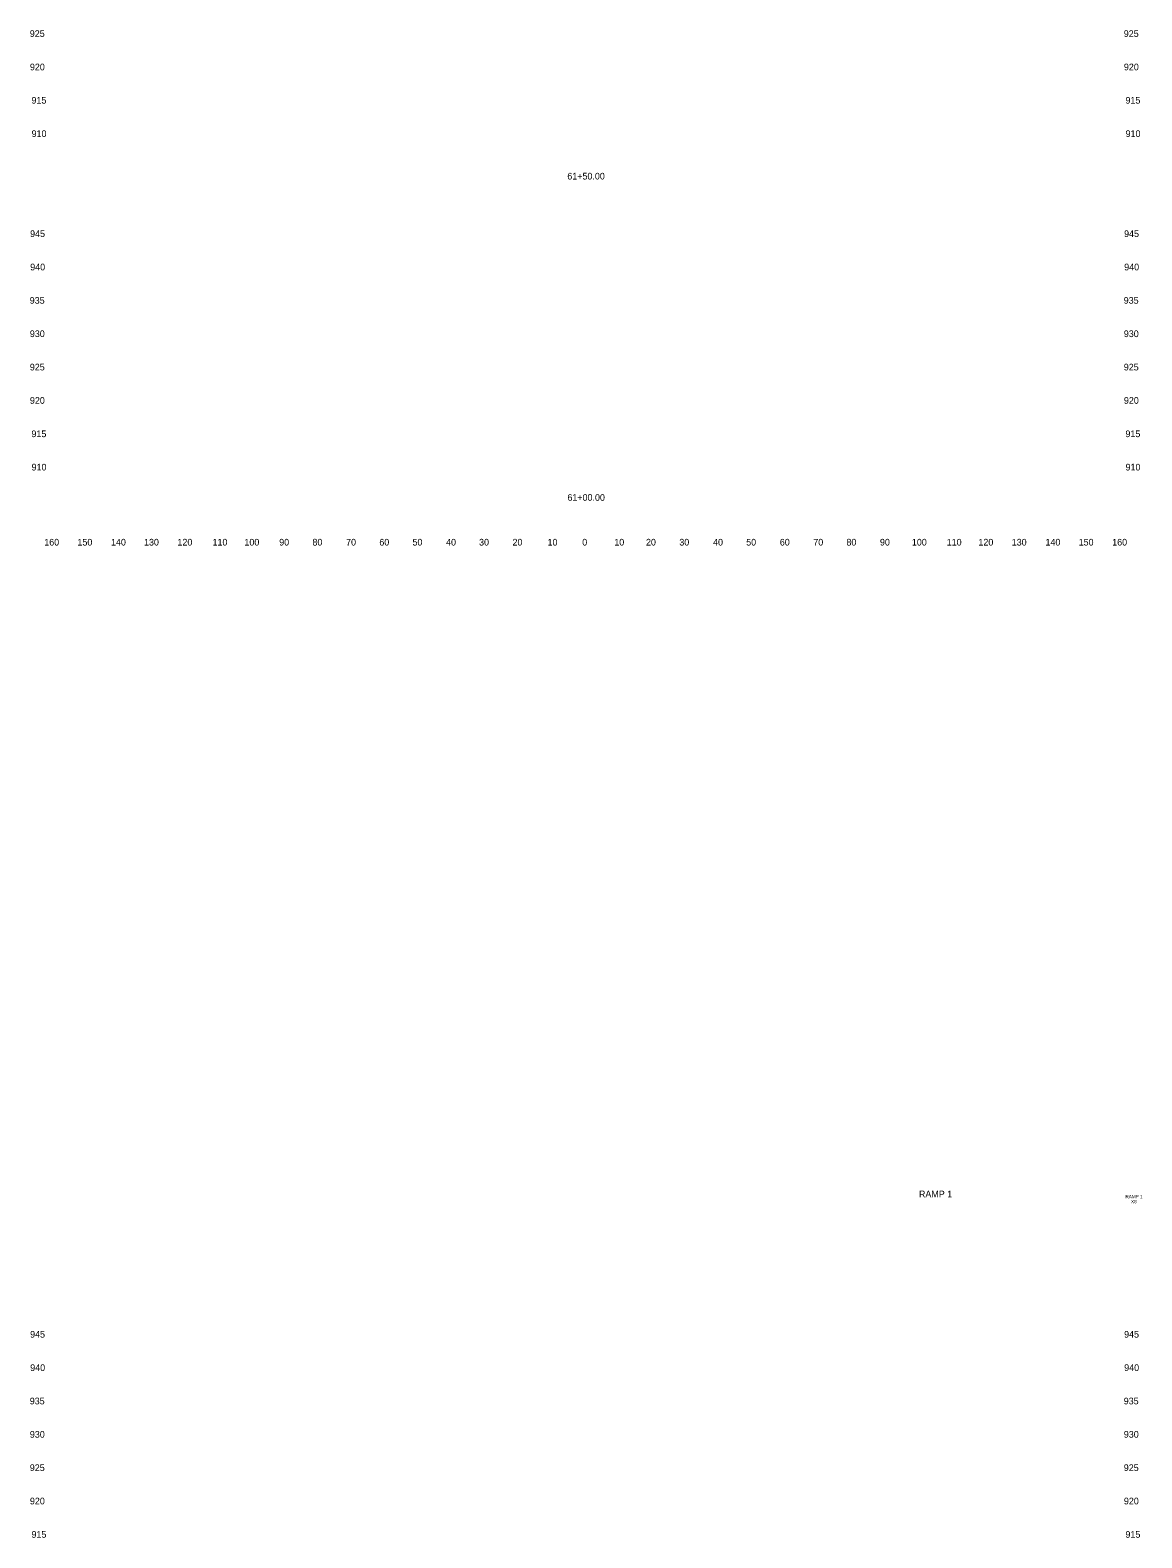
# Model space of a CAD drawing. Extents: x 4994 to 7869, y 4997 to 8804.
# Drawn here: x 4993.9 to 5327, y 7900 to 8352 of the extents above; entities that cross this region are included whole.
import ezdxf

# ---------------------------------------------------------------- set-up
doc = ezdxf.new("R2010")
doc.units = 0
for name, color, linetype in [('RD_SHT_ID', 7, 'Continuous'), ('RD_XS_TX_Offset', 7, 'Continuous'), ('RD_XS_TX_Station', 7, 'Continuous')]:
    doc.layers.add(name, color=color, linetype=linetype)

msp = doc.modelspace()

# ---------------------------------------------------------------- texts
at = {"layer": 'RD_SHT_ID'}
for s, height, p in [('RAMP 1', 2, (5260.19, 8002.06)), ('RAMP 1', 1, (5322.06, 8001.8)), ('X8', 1, (5323.74, 8000.3))]:
    msp.add_text(s, height=height, dxfattribs=at).set_placement(p)
at = {"layer": 'RD_XS_TX_Offset'}
for s, p in [('925', (4993.77, 8350)), ('925', (5321.57, 8350)), ('920', (4993.8, 8340)), ('920', (5321.6, 8340)), ('915', (4994.27, 8330)), ('915', (5322.07, 8330)), ('910', (4994.3, 8320)), ('910', (5322.1, 8320)), ('945', (4993.86, 8290)), ('945', (5321.66, 8290)), ('940', (4993.89, 8280)), ('940', (5321.69, 8280)), ('935', (4993.75, 8270)), ('935', (5321.55, 8270)), ('930', (4993.78, 8260)), ('930', (5321.58, 8260)), ('925', (4993.77, 8250)), ('925', (5321.57, 8250)), ('920', (4993.8, 8240)), ('920', (5321.6, 8240)), ('915', (4994.27, 8230)), ('915', (5322.07, 8230)), ('910', (4994.3, 8220)), ('910', (5322.1, 8220)), ('160', (4998.1, 8197.5)), ('150', (5008.04, 8197.5)), ('140', (5018.1, 8197.5)), ('130', (5027.99, 8197.5)), ('120', (5038.01, 8197.5)), ('110', (5048.51, 8197.5)), ('100', (5058.07, 8197.5)), ('90', (5068.5, 8197.5)), ('80', (5078.46, 8197.5)), ('70', (5088.54, 8197.5)), ('60', (5098.5, 8197.5)), ('50', (5108.43, 8197.5)), ('40', (5118.5, 8197.5)), ('30', (5128.39, 8197.5)), ('20', (5138.4, 8197.5)), ('10', (5148.91, 8197.5)), ('0', (5159.3, 8197.5)), ('0', (5159.3, 8197.5)), ('10', (5168.91, 8197.5)), ('20', (5178.4, 8197.5)), ('30', (5188.39, 8197.5)), ('40', (5198.5, 8197.5)), ('50', (5208.43, 8197.5)), ('60', (5218.5, 8197.5)), ('70', (5228.54, 8197.5)), ('80', (5238.46, 8197.5)), ('90', (5248.5, 8197.5)), ('100', (5258.07, 8197.5)), ('110', (5268.51, 8197.5)), ('120', (5278.01, 8197.5)), ('130', (5287.99, 8197.5)), ('140', (5298.1, 8197.5)), ('150', (5308.04, 8197.5)), ('160', (5318.1, 8197.5)), ('945', (4993.86, 7960)), ('945', (5321.66, 7960)), ('940', (4993.89, 7950)), ('940', (5321.69, 7950)), ('935', (4993.75, 7940)), ('935', (5321.55, 7940)), ('930', (4993.78, 7930)), ('930', (5321.58, 7930)), ('925', (4993.77, 7920)), ('925', (5321.57, 7920)), ('920', (4993.8, 7910)), ('920', (5321.6, 7910)), ('915', (4994.27, 7900)), ('915', (5322.07, 7900))]:
    msp.add_text(s, height=2, dxfattribs=at).set_placement(p)
at = {"layer": 'RD_XS_TX_Station'}
for s, p in [('61+50.00', (5154.83, 8307.25)), ('61+00.00', (5154.86, 8210.91))]:
    msp.add_text(s, height=2, dxfattribs=at).set_placement(p)

doc.saveas('drawing.dxf')
